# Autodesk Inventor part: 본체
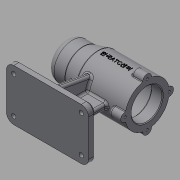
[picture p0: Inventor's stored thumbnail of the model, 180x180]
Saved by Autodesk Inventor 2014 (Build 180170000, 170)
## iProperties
Created: 2019-07
Part Number: 본체
Material: Generic
Document SubType Name: Modeling
Designer: kb542-5
Density: 1 g/cm^3
Appearance: Default
Author: kb542-5
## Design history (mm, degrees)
sketch "스케치1"
  geometry: 1 further point
sketch "스케치2"
  geometry: L1 (-56, 0)-(56, 0); L2 (-56, 0)-(-56, 25); L3 (-56, 25)-(-31, 25); L4 (-31, 25)-(-11, 30); L5 (-11, 30)-(56, 30); L6 (56, 21)-(41, 21); L7 (41, 21)-(41, 24); L8 (41, 24)-(-13, 24); L9 (-13, 24)-(-13, 21); L10 (-13, 21)-(-25, 21); L11 (-25, 21)-(-25, 17.5); L12 (-25, 17.5)-(-43, 17.5); L13 (-43, 17.5)-(-43, 16); L14 (-43, 16)-(-47, 16); L15 (-47, 16)-(-47, 10.5); L16 (-47, 10.5)-(-50, 10.5); L17 (-50, 10.5)-(-50, 0); L18 (56, 21)-(56, 30); 2 further points
  constraints: 36 end point, 12 parallel, 3 perpendicular, 2 horizontal, 1 coincident, 1 midpoint, 1 point on line, 1 vertical alignment
  dimensions: "d0" = 112 distance of L1.start L1.end; "d1" = 60 diameter of L5 L1; "d2" = 21 diameter of L16 L1; "d3" = 32 diameter of L14 L1; "d4" = 35 diameter of L12 L1; "d5" = 42 diameter of L10 L1; "d6" = 48 diameter of L8 L1; "d7" = 42 diameter of L6 L1; "d8" = 50 diameter of L3 L1; "d9" = 25 distance of L3.end L2.end; "d10" = 45 horizontal distance of L4.end L2.end; "d11" = 15 distance of L6.start L6.end; "d12" = 54 distance of L7.end L8.end; "d13" = 12 distance of L9.end L10.end; "d14" = 18 distance of L11.end L12.end; "d15" = 4 distance of L13.end L14.end; "d16" = 3 distance of L15.end L16.end
revolve "회전1" sketch "스케치2" stored, may be unused: angle "d17" = 90 deg
sketch "스케치3"
  geometry: A1 r 30 centre (0, 0) between (0, 30) and (-5.97, 29.4) reference; A2 r 6 centre (0, 30) between (5.97, 29.4) and (-5.97, 29.4); 1 further point
  constraints: 5 point on circle, 1 centre point, 1 vertical alignment
  dimensions: "d18" = 6 radius of A2
extrude "돌출1" join sketch "스케치3" distance "d19" = 16; taper "d20" = 0 deg
fillet "모깎기1" dims "d21" = 3
fillet "모깎기2" dims "d22" = 1, "d26" = 3
node "작업 평면1"
sketch "스케치4"
  geometry: L1 (56, 35)-(-56, 35); L2 (-56, 35)-(-56, -35); L3 (-56, -35)-(56, -35); L4 (56, -35)-(56, 35); L5 (56, 35)-(-56, -35); L6 (-56, 35)-(56, -35); 1 further point
  constraints: 12 end point, 2 midpoint, 2 parallel, 1 horizontal, 1 perpendicular
  dimensions: "d28" = 112 distance of L2.end L3.end; "d29" = 70 distance of L1.end L2.end
extrude "돌출2" join sketch "스케치4" distance "d30" = 10; taper "d31" = 0 deg
fillet "모깎기3" dims "d32" = 10
sketch "스케치5"
  geometry: L1 (-22.666, 19.654)-(-70, 28); L2 (-70, 35)-(-70, 25) reference; L3 (-22.666, -19.654)-(-70, -28); L4 (-70, -25)-(-70, -35) reference; L5 (-70, -25)-(-70, 25) reference; L6 (0, 0)-(-70, 0); A1 r 30 centre (0, 0) between (-22.666, 19.654) and (-22.666, -19.654) reference; 1 further point
  constraints: 6 end point, 2 point on circle, 2 point on line, 1 midpoint, 1 other
  dimensions: "d33" = 7 distance of L1.end L2.start; "d34" = 100 deg angle of L2 L1
extrude "돌출3" join sketch "스케치5" stored distance "d35" = 8; taper "d36" = 0 deg
sketch "스케치6"
  geometry: L1 (-11, -30)-(39, -30) reference; L2 (31, -30)-(31, -70); L3 (46, -70)-(-46, -70) reference; L4 (56, -70)-(56, -80) reference; L5 (-31, -25)-(-11, -30) reference; L6 (-20.57, -27.607)-(-36, -70); L7 (-56, -80)-(-56, -70) reference; 1 further point
  constraints: 4 end point, 4 point on line, 1 vertical
  dimensions: "d37" = 25 distance between parallel lines of L4 L2; "d38" = 20 distance from line of L6.end L7; "d39" = 110 deg angle of L3 L6
feature "리브1" dims "d40" = 1, "d41" = 8, "d42" = 0, "d43" = 0, "d44" = 1, "d45" = 1
feature "리브2" dims "d46" = 1, "d47" = 8, "d48" = 0, "d49" = 0, "d50" = 1, "d51" = 1
sketch "스케치7"
  geometry: L1 (46, 35)-(-46, 35) reference; L2 (-56, 25)-(-56, -25) reference; L3 (46, 35)-(-46, 35) reference; L4 (56, -25)-(56, 25) reference; L5 (-46, -35)-(46, -35) reference; A1 r 10 centre (-46, 25) between (-46, 35) and (-56, 25) reference; A2 r 10 centre (46, 25) between (56, 25) and (46, 35) reference; A3 r 10 centre (46, -25) between (46, -35) and (56, -25) reference; A4 r 10 centre (-46, -25) between (-56, -25) and (-46, -35) reference; 5 further points
  constraints: 4 coincident
hole "구멍1" sketch "스케치7" at (-46, 25), (-46, -25), (46, -25), (46, 25) diameter "d52" = 6; stored, may be unused: countersink angle "d56" = 90 deg, drill point angle "d58" = 118 deg; dims "d53" = 6, "d54" = 4, "d55" = 2, "d57" = 8
chamfer "모따기1" distance "d59" = 3; stored, may be unused: second distance "d60" = 2, angle "d61" = 45 deg
chamfer "모따기2" distance "d62" = 1; stored, may be unused: second distance "d63" = 2, angle "d64" = 45 deg
fillet "모깎기4" dims "d65" = 0.3, "d66" = 3
fillet "모깎기5" dims "d67" = 10, "d68" = 3
fillet "모깎기6" dims "d69" = 3
sketch "스케치8"
  geometry: C1 r 22 at (0, -30) reference; A1 r 6 centre (0, -60) between (-5.998, -60.171) and (5.998, -60.171) reference; A2 r 1 centre (6.997, -60.2) between (6.771, -59.226) and (5.998, -60.171) reference; A3 r 30 centre (0, -30) between (6.771, -59.226) and (29.226, -36.771) reference; A4 r 1 centre (30.2, -36.997) between (30.171, -35.998) and (29.226, -36.771) reference; A5 r 6 centre (30, -30) between (30.171, -35.998) and (30.171, -24.002) reference; A6 r 1 centre (30.2, -23.003) between (29.226, -23.229) and (30.171, -24.002) reference; A7 r 30 centre (0, -30) between (29.226, -23.229) and (6.771, -0.774) reference; A8 r 1 centre (6.997, 0.2) between (5.998, 0.171) and (6.771, -0.774) reference; A9 r 6 centre (0, 0) between (5.998, 0.171) and (-5.998, 0.171) reference; A10 r 1 centre (-6.997, 0.2) between (-6.771, -0.774) and (-5.998, 0.171) reference; A11 r 30 centre (0, -30) between (-6.771, -0.774) and (-29.226, -23.229) reference; A12 r 1 centre (-30.2, -23.003) between (-30.171, -24.002) and (-29.226, -23.229) reference; A13 r 6 centre (-30, -30) between (-30.171, -24.002) and (-30.171, -35.998) reference; A14 r 1 centre (-30.2, -36.997) between (-29.226, -36.771) and (-30.171, -35.998) reference; A15 r 30 centre (0, -30) between (-29.226, -36.771) and (-6.771, -59.226) reference; A16 r 1 centre (-6.997, -60.2) between (-5.998, -60.171) and (-6.771, -59.226) reference; 5 further points
  constraints: 4 coincident
hole "구멍2" sketch "스케치8" at (0, 0), (-30, -30), (30, -30), (0, -60) diameter "d70" = 3.242; stored, may be unused: countersink angle "d74" = 90 deg, drill point angle "d76" = 118 deg; dims "d71" = 8, "d72" = 4, "d73" = 2, "d75" = 11
node "작업 평면2"
sketch "스케치9"
  geometry: L1 (56, 6.771)-(56, 29.226) reference; 2 further points
  constraints: 1 horizontal alignment, 1 other
  dimensions: "d78" = 42 distance from line of L1 point (14, 0)
feature "엠보싱1" sketch "스케치9" dims "d0" = 112, "d1" = 60, "d2" = 21, "d3" = 32, "d4" = 35, "d5" = 42, "d6" = 48, "d7" = 42, "d8" = 50, "d9" = 25, "d10" = 45, "d11" = 15, "d12" = 54, "d13" = 12, "d14" = 18, "d15" = 4, "d16" = 3, "d79" = 0.5, "d80" = 0
node "솔리드1"
pattern_circular "원형 패턴1" dims "d24" = 360 deg
node "투영된 루프1"
node "투영된 루프2"
